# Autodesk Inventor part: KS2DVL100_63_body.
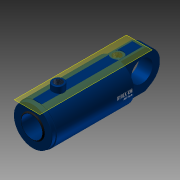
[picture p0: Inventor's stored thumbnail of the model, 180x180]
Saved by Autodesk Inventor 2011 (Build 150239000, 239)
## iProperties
Created: 2010-11
Document SubType Name: Modeling
Designer: TB
Mass: 405.061 g
Surface Area: 916.939 cm^2
Volume: 405.061 cm^3
Density: 1 g/cm^3
Author: TB
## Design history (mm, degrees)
sketch "Sketch2"
  geometry: L1 (-35, -3)-(-35, 3); L2 (-35, -9)-(-35, 9); L3 (-35, 0)-(-35, 60); L4 (-35, 60)-(-266, 60); L5 (-266, 60)-(-266, 57.5); L6 (-266, 57.5)-(-278, 57.5); L7 (-278, 57.5)-(-278, 35.5); L8 (-278, 35.5)-(-281, 32.5); L9 (-281, 32.5)-(-281, 31.5); L10 (-281, 31.5)-(-198, 31.5); L11 (-198, 31.5)-(-198, 50); L12 (-198, 50)-(-58, 50); L13 (-58, 50)-(-58, 0); L14 (-58, 0)-(-35, 0); L15 (-58, 0)-(-148.421, 0); L16 (-35, 9)-(-32, 12) reference; L17 (-32, 12)-(-35, 12) reference; L18 (-35, 12)-(-35, 9) reference; L19 (-32, 12)-(-35, 9) reference; L20 (-32, 12)-(-35, 12) reference; L21 (-35, 9)-(-35, 12) reference; L22 (-35, 9)-(-32, 12) reference; 1 further point
  constraints: 44 end point, 8 perpendicular, 6 parallel, 5 collinear, 2 horizontal, 2 vertical, 1 coincident, 1 midpoint, 1 point on line, 10 other
  dimensions: "DiaY" = 120 diameter of L4 L15; "DiaI" = 100 diameter of L12 L15; "d4" = 1 distance of L8.end L9.end; "d5" = 45 deg angle of L10 L8; "d6" = 3 distance between parallel lines of L7 L9; "DiaStang" = 63 diameter of L10 L15; "RindDia" = 115 diameter of L6 L15; "RingLengde" = 12 distance of L5.end L6.end; "RingTykk" = 80 distance between parallel lines of L11 L7; "KroppLengde" = 243 distance between parallel lines of L7 L3 (derived); "BunnTykkelse" = 23 distance between parallel lines of L13 L3
revolve "Kropp" sketch "Sketch2" stored, may be unused: angle "d13" = 90 deg
sketch "Sketch3"
  geometry: L1 (-58, -50)-(-58, 50) reference; L2 (-58, 0.01)-(-158, 0.01); L3 (-158, -0.01)-(-58, -0.01); A1 r 0.01 centre (-158, 0) between (-158, 0.01) and (-158, -0.01); A2 r 0.01 centre (-58, 0) between (-58, -0.01) and (-58, 0.01); 2 further points
  constraints: 4 end point, 4 point on circle, 4 tangent, 2 centre point, 1 coincident, 1 midpoint, 1 parallel, 1 perpendicular
  dimensions: "d17" = 0.01 radius of A2; "d18" = 100 distance of L2.start L2.end (= Slaglengde)
feature "BaneTransitionalConstraint" sketch "Sketch3" dims "d19" = 2, "d20" = 0
sketch "Sketch6"
  geometry: L1 (-84, 0)-(84, 0) reference; L2 (13.332, 58.5)-(-11.843, 58.5); L3 (60, 0)-(60, 31.248); L4 (-60, 0)-(-60, -18.451); A1 r 60 centre (0, 0) between (-60, 0) and (60, 0) reference; 2 further points
  constraints: 6 end point, 2 point on circle, 2 vertical, 2 other
  dimensions: "d30" = 58.5 distance from line of point (0, 0) L2 (computed from DiaY); "d31" = 0 deg angle of L1 L2 (computed from Vinkel_Plussport); "d37" = 90 deg angle of L2 L3; "d38" = 90 deg angle of L2 L4
  node "Projected Loop3"
workplane "Work Plane5"
sketch "Sketch7"
  geometry: L1 (13.332, -337.2)-(13.332, 56.2) reference; L2 (-19.633, -35)-(38.367, -35) reference; C1 r 17.5 at (13.332, -52.5); 1 further point
  constraints: 1 centre point, 1 point on line
  dimensions: "PortDia" = 35 diameter of C1
extrude "Extrusion2" cut sketch "Sketch7" stored distance "d34" = 1.5; taper "d35" = 0 deg
workplane "Work Plane7"
sketch "Sketch4"
  geometry: L1 (-16.68, -40)-(-16.68, -78.777); L2 (-16.68, -78.777)-(16.68, -78.777); L3 (16.68, -78.777)-(16.68, -40); L4 (16.68, -40)-(-16.68, -40); L5 (-40.643, -40)-(0, -40); L6 (-29, -35)-(29, -35); L7 (0, -35)-(0, -40); 2 further points
  constraints: 6 end point, 2 midpoint, 2 other
  dimensions: "d40" = 5 distance of L7.start L5.end
emboss "Emboss1" sketch "Sketch4" dims "d4" = 1, "d5" = 45 deg, "d6" = 3, "d22" = 0.2, "d23" = 0, "DiaI" = 100, "DiaY" = 120, "RindDia" = 115, "DiaStang" = 63, "RingTykk" = 80, "RingLengde" = 12, "KroppLengde" = 243 (derived), "BunnTykkelse" = 23
workplane "Work Plane8"
sketch "Sketch8"
  geometry: L1 (-29, -35)-(29, -35); L2 (0, -35)-(0, -40); L3 (-5.906, -110.587)-(-5.906, -40); L4 (-5.906, -40)-(5.906, -40); L5 (5.906, -40)-(5.906, -110.587); L6 (5.906, -110.587)-(-5.906, -110.587); L7 (60, -35)-(-60, -35); L8 (60, -35)-(-60, -35) reference; 3 further points
  constraints: 6 end point, 4 midpoint, 2 other
  dimensions: "d42" = 5 distance of L2.start L2.end
emboss "Emboss2" sketch "Sketch8" dims "d4" = 1, "d5" = 45 deg, "d6" = 3, "d43" = 0.2, "d44" = 0, "DiaI" = 100, "DiaY" = 120, "RindDia" = 115, "DiaStang" = 63, "RingTykk" = 80, "RingLengde" = 12, "KroppLengde" = 243 (derived), "BunnTykkelse" = 23
sketch "Sketch9"
  geometry: A1 r 12.5 centre (9.367, -52.5) between (0, -60.776) and (18.735, -60.776) reference; 1 further point
hole "Hole1" sketch "Sketch9" at (9.367, -52.5) diameter "d45" = 14.95; stored, may be unused: countersink angle "d49" = 82 deg, drill point angle "d51" = 118 deg; dims "d46" = 6, "d47" = 3.023, "d48" = 2, "DiaInvPluss" = 24.5
workplane "Work Plane9"
sketch "Sketch10"
  geometry: L1 (-84, 0)-(84, 0) reference; L2 (0, 60)-(13.136, 60); L3 (0, 60)-(0, 31.79); L4 (17.5, 57.391)-(17.5, 77.5); L5 (17.5, 77.5)-(0, 77.5); L6 (0, 77.5)-(0, 60); L7 (0, 60)-(17.5, 57.391); C1 r 60 at (0, 0) reference; A1 r 60 centre (0, 0) between (0, 60) and (17.5, 57.391); 1 further point
  constraints: 12 end point, 4 perpendicular, 2 concentric, 2 point on circle, 1 centre point, 1 point on line, 1 tangent
  dimensions: "d53" = 0 deg angle of L1 L2 (computed from Vinkel_Minusport); "DiaUtvStussMinus" = 35 diameter of L4 L3; "HøydeStussMinuss" = 17.5 distance between parallel lines of L2 L5
revolve "Revolution2" sketch "Sketch10" stored, may be unused: angle "d56" = 90 deg
hole "Hole2" diameter "d59" = 24.117; stored, may be unused: countersink angle "d63" = 82 deg, drill point angle "d65" = 118 deg; dims "d57" = 10, "d58" = 10, "d60" = 6, "d61" = 3.023, "d62" = 2, "DiaInvStussMinus" = 24.5
fillet "Fillet1" dims "d66" = 2
sketch "Sketch15"
  geometry: L1 (20, -56.569)-(20, 56.569); L2 (-20, -56.569)-(-20, 56.569); L3 (0, 84)-(0, -84) reference; A1 r 60 centre (0, 0) between (20, -56.569) and (-20, -56.569) reference; A2 r 60 centre (0, 0) between (20, 56.569) and (-20, 56.569); A3 r 60 centre (0, 0) between (-20, -56.569) and (20, -56.569)
  constraints: 8 point on circle, 4 end point, 4 point on line, 2 centre point, 2 concentric, 2 parallel, 1 coincident
  dimensions: "EyeBunnTykk" = 20 distance from line of L1 A1.centre; "EyeBunnTykk2" = 20 distance from line of A1.centre L2
extrude "Extrusion6" join sketch "Sketch15" taper "d98" = 0 deg; distance "LengdeEyeMinussBunntykk" = 116
sketch "Sketch16"
  geometry: L1 (-266, 60)-(81, 60) reference; L2 (-266, -60)-(81, -60) reference; L3 (-266, 60)-(81, 60) reference; L4 (81, 60)-(81, 56.569) reference; L5 (81, -56.569)-(81, 56.569) reference; L6 (-337.554, 0)-(163.323, 0) reference; L7 (29, 60)-(81, 60); L8 (81, 60)-(81, 8); A1 r 52 centre (29, 8) between (81, 8) and (29, 60); 6 further points; 2 other entities
  constraints: 4 end point, 4 tangent, 2 point on circle, 2 point on line, 1 centre point, 1 collinear, 1 perpendicular, 2 other
  dimensions: "d137" = 8 distance from line of L8.end L6
extrude "Extrusion7" cut sketch "Sketch16" taper "d102" = 0 deg; stored distance "ExtruEyeBunn" = 40
mirror "Mirror1"
sketch "Sketch20"
  geometry: L1 (-266, 60)-(81, 60) reference; L2 (81, -56.569)-(81, 56.569) reference; L3 (81, 60)-(81, 56.569) reference; L4 (-336.202, 0)-(155.214, 0) reference; L5 (-35, -56.569)-(-35, 56.569) reference; L6 (-35, 0)-(28, 0); L7 (28, 0)-(28, 20.918); L8 (54.968, 46.709)-(37.254, 56.936); A1 r 53.935 centre (28, 0) between (81, 10) and (54.968, 46.709); A2 r 30 centre (23.993, 30.026) between (37.254, 56.936) and (25.252, 60); 1 further point
  constraints: 6 end point, 4 point on circle, 3 point on line, 2 centre point, 1 coincident, 1 midpoint, 1 perpendicular, 1 tangent
  dimensions: "d147" = 63 distance of L6.start L6.end; "d157" = 10 distance from line of L4 A1.start; "d158" = 30 deg angle of L1 L8; "d159" = 30 radius of A2
extrude "Extrusion10" cut sketch "Sketch20" stored distance "d144" = 10; taper "d145" = 0 deg
mirror "Mirror2"
sketch "Sketch17"
  geometry: L1 (113.137, 0)-(0, 0) reference; L2 (56.569, -318.4)-(56.569, 188.4) reference; C1 r 32 at (56.569, 63); 1 further point
  constraints: 1 centre point, 1 point on line
  dimensions: "DiaHullEyeBunn" = 64 diameter of C1; "d125" = 63 distance from line of C1.centre L1
extrude "Extrusion8" cut sketch "Sketch17" taper "d105" = 0 deg; distance "ExtruHullEye" = 40
pattern_circular "Circular Pattern1 Only Subsea" dims "d108" = 180 deg (derived)
workplane "Work Plane11"
sketch "Sketch18"
  geometry: L1 (0, -69.6)-(0, 11.6) reference; L2 (50, -58)-(-50, -58) reference; L3 (50, -58)-(-50, -58) reference; C1 r 17.5 at (0, -26); 1 further point
  constraints: 1 centre point
  dimensions: "DiaForsenkPlussPort" = 35 diameter of C1; "PlassPlussport" = 32 distance from line of L2 C1.centre
extrude "Extrusion9" cut sketch "Sketch18" stored distance "d113" = 10; taper "d114" = 0 deg
sketch "Sketch19"
  geometry: 10 further points
  constraints: 1 other
hole "Hole3" sketch "Sketch19" at (0, -26) diameter "d115" = 24.117; stored, may be unused: countersink angle "d119" = 90 deg, drill point angle "d121" = 118 deg; dims "d116" = 6, "d117" = 4, "d118" = 2, "d120" = 14.5
pattern_circular "Circular Pattern2 Only Subsea" dims angle "d123" = 360 deg
body "Solid1"
chamfer "Chamfer" distance "Chamfer" = 1; stored, may be unused: second distance "d15" = 2, angle "d16" = 45 deg
node "Projected Loop2"
body "Srf1"
node "Projected Loop10"
other parameters: "Slaglengde" = 100, "Forlengelse_rør" = 0, "Vinkel_Plussport" = 0 [user parameter; used in 1 equation term], "Vinkel_Minusport" = 0, "d32" = 90 deg, "d39" = 90 deg, "d41" = 90 deg, "PortMinusPlass" = -76, "Minusport2" = 180 deg, "ForsenkningPlussPort" = 58.2 (derived)
